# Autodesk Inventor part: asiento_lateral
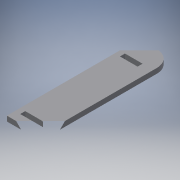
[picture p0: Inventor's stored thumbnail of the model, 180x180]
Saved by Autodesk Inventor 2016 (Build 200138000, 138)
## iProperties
Created: 2017-06
Part Number: asiento_lateral
Material: Generic
Document SubType Name: Modeling
Designer: laboratorioesan
Density: 1 g/cm^3
Appearance: Default
Author: laboratorioesan
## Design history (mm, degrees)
sketch "Sketch1"
  geometry: L1 (27.824, 0)-(92.824, 0) reference; L2 (92.824, 0)-(92.824, 18.5) reference; L3 (27.824, 18.5)-(92.824, 18.5) reference; L4 (27.824, 0)-(27.824, 18.5) reference; L5 (132.824, 0)-(132.824, 18.5) reference; L6 (92.824, -350)-(27.824, -350) reference; L7 (27.824, -350)-(27.824, -368.5) reference; L8 (92.824, -368.5)-(27.824, -368.5) reference; L9 (92.824, -350)-(92.824, -368.5) reference; L10 (132.824, -350)-(132.824, -368.5) reference; L11 (-526.937, -398.5)-(8.357, -398.5) reference; L12 (132.824, 91.5)-(8.324, 91.5); L13 (8.324, 91.5)-(8.324, -398.5); L14 (8.324, -398.5)-(132.824, -398.5); L15 (132.824, -398.5)-(132.824, 91.5); L16 (8.357, 91.5)-(-526.937, 91.5) reference; 1 further point
  constraints: 8 end point, 2 horizontal alignment, 2 parallel, 1 horizontal, 1 perpendicular, 1 vertical alignment
  dimensions: "d0" = 124.5 distance of L13.end L14.end
extrude "Extrusion1" new body sketch "Sketch1" distance "d1" = 18.5; taper "d2" = 0 deg
fillet "Fillet1" dims "d3" = 60
body "Solid1"
node "Reference1"
node "Reference2"
node "Reference3"
node "Reference4"
node "Reference5"
node "Reference6"
